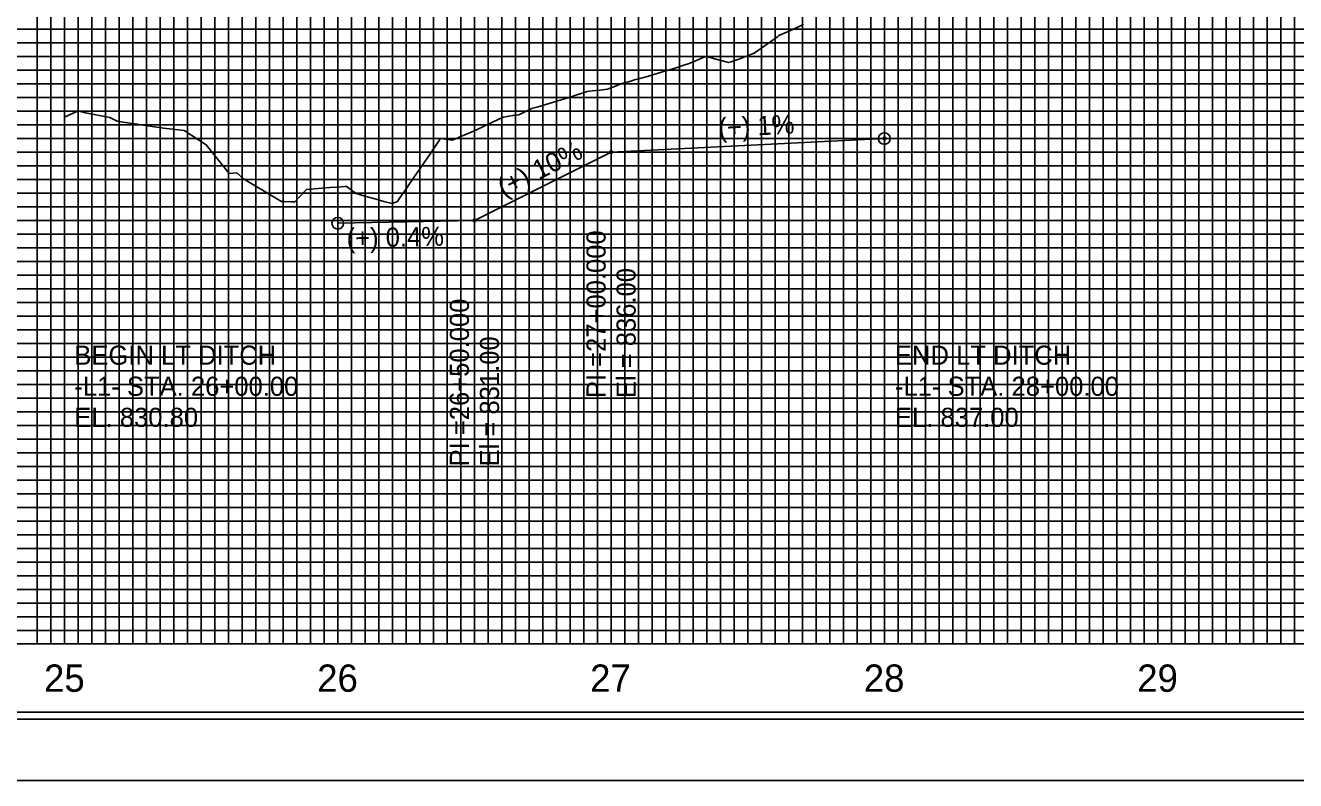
# Model space of a CAD drawing. Extents: x 570622 to 580296, y -55533 to -48575.
# Drawn here: x 570874.4 to 571339.1, y -53332.1 to -53055.6 of the extents above; entities that cross this region are included whole.
import ezdxf

# ---------------------------------------------------------------- set-up
doc = ezdxf.new("R2010")
doc.units = 0
for name, color, linetype in [('Exist Vertical Profile Ground Line', 7, 'Continuous'), ('Exist Vertical Profile Horizontal Axis Label Major', 7, 'Continuous'), ('Prop Vertical Profile Ditch Grade Left', 7, 'Continuous'), ('Prop Vertical Profile Ditch Grade Left Label', 7, 'Continuous'), ('Prop VPI Ditch Grade Left Label', 7, 'Continuous'), ('Sheet Cutting Line CELL', 7, 'Continuous'), ('Sheet DOT Grid CELL', 7, 'Continuous'), ('Sheet Layout Profile Border Port 2', 7, 'Continuous'), ('Sheet Plot Border Inside CELL', 7, 'Continuous'), ('Sheet Plot Border Outside CELL', 7, 'Continuous'), ('Sheet Profile CELL', 7, 'Continuous'), ('Sheet Profile Grid Major CELL', 7, 'Continuous'), ('Sheet Profile Grid Middle CELL', 7, 'Continuous'), ('Sheet Profile Grid Minor CELL', 7, 'Continuous')]:
    doc.layers.add(name, color=color, linetype=linetype)

msp = doc.modelspace()

# ---------------------------------------------------------------- linework, layer by layer
at = {"layer": 'Exist Vertical Profile Ground Line'}
msp.add_lwpolyline([(570888.69, -53089.16), (570893.66, -53086.84), (570896.35, -53087.58), (570905.28, -53089.28), (570907.95, -53090.63), (570909.32, -53090.91), (570911.07, -53091.22), (570924.97, -53093.18), (570932.45, -53094.08), (570940.58, -53099.31), (570948.99, -53109.85), (570951.75, -53109.6), (570954.16, -53111.83), (570966, -53118.85), (570968.09, -53120.08), (570968.82, -53120.11), (570971.65, -53120.22), (570972.95, -53120.26), (570974.47, -53118.62), (570977.29, -53115.65), (570980.12, -53115.45), (570982.94, -53115.24), (570985.77, -53115.01), (570988.59, -53114.78), (570991.41, -53114.53), (570991.81, -53114.49), (570994.24, -53116.27), (570995.48, -53117.17), (570997.06, -53117.64), (570999.89, -53118.47), (571002.71, -53119.27), (571005.53, -53120.06), (571008.57, -53120.87), (571010.53, -53120.07), (571011.18, -53119.14), (571014, -53115.06), (571016.83, -53110.95), (571019.65, -53106.82), (571022.48, -53102.66), (571025.3, -53098.47), (571026.24, -53097.06), (571028.12, -53097.3), (571030.64, -53097.59), (571030.95, -53097.46), (571033.77, -53096.27), (571036.59, -53095.04), (571039.42, -53093.79), (571042.24, -53092.51), (571045.07, -53091.21), (571047.89, -53089.88), (571049.39, -53089.16), (571050.71, -53088.97), (571053.54, -53088.53), (571054.92, -53088.31), (571056.36, -53087.62), (571059.19, -53086.26), (571059.61, -53086.05), (571062.01, -53085.38), (571064.83, -53084.57), (571067.66, -53083.74), (571070.48, -53082.87), (571073.3, -53081.98), (571076.13, -53081.06), (571078.95, -53080.12), (571079.89, -53079.79), (571081.78, -53079.6), (571084.6, -53079.29), (571087.42, -53078.9), (571090.25, -53077.83), (571092.65, -53076.91), (571093.07, -53076.79), (571095.89, -53076), (571097.3, -53075.59), (571098.72, -53075.2), (571101.54, -53074.41), (571104.37, -53073.59), (571107.19, -53072.75), (571110.01, -53071.88), (571112.84, -53070.99), (571115.66, -53070.07), (571116.91, -53069.65), (571118.49, -53069.02), (571121.31, -53067.88), (571123.57, -53066.94), (571124.13, -53067.11), (571126.96, -53067.93), (571129.78, -53068.72), (571131.68, -53069.23), (571132.6, -53068.92), (571135.43, -53067.93), (571138.25, -53066.93), (571141.08, -53065.82), (571143.9, -53063.83), (571146.72, -53061.81), (571149.55, -53059.78), (571150.11, -53059.37), (571152.37, -53058.35), (571155.19, -53057.06), (571158.02, -53055.74), (571159.14, -53055.21)], dxfattribs=at)
at = {"layer": 'Prop Vertical Profile Ditch Grade Left'}
msp.add_lwpolyline([(570988.69, -53128.05), (571038.69, -53127.05), (571088.69, -53102.05), (571188.69, -53097.05)], dxfattribs=at)
at = {"layer": 'Prop Vertical Profile Ditch Grade Left Label'}
for p, q in [((571188.69, -53098.05), (571188.69, -53182.05)), ((571088.69, -53103.05), (571088.69, -53196.19)), ((570988.69, -53128.05), (570988.69, -53182.05)), ((570988.69, -53182.05), (570889.59, -53182.05)), ((571287.94, -53182.05), (571188.69, -53182.05))]:
    msp.add_line(p, q, dxfattribs=at)
at = {"layer": 'Prop VPI Ditch Grade Left Label'}
for centre, radius in [((571188.69, -53097.05), 2.14), ((571188.69, -53097.05), 0.5), ((571088.69, -53102.05), 0.5), ((570988.69, -53128.05), 2.14), ((571038.69, -53127.05), 0.5)]:
    msp.add_circle(centre, radius, dxfattribs=at)
at = {"layer": 'Sheet Cutting Line CELL'}
msp.add_line((570621.69, -53332.05), (572305.69, -53332.05), dxfattribs=at)
at = {"layer": 'Sheet DOT Grid CELL'}
for p, q in [((570888.69, -52782.05), (570888.69, -53282.05)), ((570938.69, -52782.05), (570938.69, -53282.05)), ((570988.69, -52782.05), (570988.69, -53282.05)), ((571038.69, -52782.05), (571038.69, -53282.05)), ((571088.69, -52782.05), (571088.69, -53282.05)), ((571138.69, -52782.05), (571138.69, -53282.05)), ((571188.69, -52782.05), (571188.69, -53282.05)), ((571238.69, -52782.05), (571238.69, -53282.05)), ((571288.69, -52782.05), (571288.69, -53282.05)), ((571338.69, -52782.05), (571338.69, -53282.05)), ((570788.69, -53082.05), (572288.57, -53082.05)), ((570788.69, -53132.05), (572288.57, -53132.05)), ((570788.69, -53182.05), (572288.57, -53182.05)), ((570788.69, -53232.05), (572288.57, -53232.05))]:
    msp.add_line(p, q, dxfattribs=at)
at = {"layer": 'Sheet Layout Profile Border Port 2'}
msp.add_lwpolyline([(570838.69, -52782.05), (572238.69, -52782.05), (572238.69, -53282.05), (570838.69, -53282.05)], close=True, dxfattribs=at)
at = {"layer": 'Sheet Plot Border Inside CELL'}
msp.add_lwpolyline([(570634.69, -53309.6), (572301.19, -53309.6), (572301.19, -52254.5), (570634.69, -52254.5)], close=True, dxfattribs=at)
at = {"layer": 'Sheet Plot Border Outside CELL'}
msp.add_lwpolyline([(570621.69, -53332.05), (572305.69, -53332.05), (572305.69, -52232.05), (570621.69, -52232.05)], close=True, dxfattribs=at)
at = {"layer": 'Sheet Profile CELL'}
for p, q in [((572288.69, -53282.05), (570788.69, -53282.05)), ((570788.69, -53307.05), (572288.69, -53307.05))]:
    msp.add_line(p, q, dxfattribs=at)
msp.add_lwpolyline([(572288.69, -52257.05), (570788.69, -52257.05), (570788.69, -53307.05), (572288.69, -53307.05)], close=True, dxfattribs=at)
at = {"layer": 'Sheet Profile Grid Major CELL'}
for points in [[(570838.69, -52782.05), (570838.69, -53282.05), (570888.69, -53282.05), (570888.69, -52782.05), (570938.69, -52782.05), (570938.69, -53282.05), (570988.69, -53282.05), (570988.69, -52782.05), (571038.69, -52782.05), (571038.69, -53282.05), (571088.69, -53282.05), (571088.69, -52782.05), (571138.69, -52782.05), (571138.69, -53282.05), (571188.69, -53282.05), (571188.69, -52782.05), (571238.69, -52782.05), (571238.69, -53282.05), (571288.69, -53282.05), (571288.69, -52782.05), (571338.69, -52782.05), (571338.69, -53282.05), (571388.69, -53282.05)], [(572288.69, -53082.05), (570788.69, -53082.05), (570788.69, -53132.05), (572288.69, -53132.05)], [(572288.69, -53182.05), (570788.69, -53182.05), (570788.69, -53182.05), (570788.69, -53232.05), (572288.69, -53232.05)], [(572288.69, -53282.05), (570788.69, -53282.05)]]:
    msp.add_lwpolyline(points, dxfattribs=at)
at = {"layer": 'Sheet Profile Grid Middle CELL'}
for points in [[(570813.69, -52782.05), (570863.69, -52782.05), (570863.69, -53282.05), (570913.69, -53282.05), (570913.69, -52782.05), (570963.69, -52782.05), (570963.69, -53282.05), (571013.69, -53282.05), (571013.69, -52782.05), (571063.69, -52782.05), (571063.69, -53282.05), (571113.69, -53282.05), (571113.69, -52782.05), (571163.69, -52782.05), (571163.69, -53282.05), (571213.69, -53282.05), (571213.69, -52782.05), (571263.69, -52782.05), (571263.69, -53282.05), (571313.69, -53282.05), (571313.69, -52782.05), (571363.69, -52782.05)], [(572288.69, -53057.05), (570788.69, -53057.05), (570788.69, -53107.05), (572288.69, -53107.05)], [(572288.69, -53157.05), (570788.69, -53157.05), (570788.69, -53207.05), (572288.69, -53207.05)], [(572288.69, -53257.05), (570788.69, -53257.05)]]:
    msp.add_lwpolyline(points, dxfattribs=at)
at = {"layer": 'Sheet Profile Grid Minor CELL'}
for p, q in [((570838.69, -53062.05), (572238.69, -53062.05)), ((572238.69, -53067.05), (570838.69, -53067.05)), ((570838.69, -53072.05), (572238.69, -53072.05)), ((572238.69, -53077.05), (570838.69, -53077.05)), ((570838.69, -53087.05), (572238.69, -53087.05)), ((572238.69, -53092.05), (570838.69, -53092.05)), ((570838.69, -53097.05), (572238.69, -53097.05)), ((572238.69, -53102.05), (570838.69, -53102.05)), ((570838.69, -53112.05), (572238.69, -53112.05)), ((572238.69, -53117.05), (570838.69, -53117.05)), ((570838.69, -53122.05), (572238.69, -53122.05)), ((572238.69, -53127.05), (570838.69, -53127.05)), ((570838.69, -53137.05), (572238.69, -53137.05)), ((572238.69, -53142.05), (570838.69, -53142.05)), ((570838.69, -53147.05), (572238.69, -53147.05)), ((572238.69, -53152.05), (570838.69, -53152.05)), ((570838.69, -53162.05), (572238.69, -53162.05)), ((572238.69, -53167.05), (570838.69, -53167.05)), ((570838.69, -53172.05), (572238.69, -53172.05)), ((572238.69, -53177.05), (570838.69, -53177.05)), ((570838.69, -53187.05), (572238.69, -53187.05)), ((572238.69, -53192.05), (570838.69, -53192.05)), ((570838.69, -53197.05), (572238.69, -53197.05)), ((572238.69, -53202.05), (570838.69, -53202.05)), ((570838.69, -53212.05), (572238.69, -53212.05)), ((572238.69, -53217.05), (570838.69, -53217.05)), ((570838.69, -53222.05), (572238.69, -53222.05)), ((572238.69, -53227.05), (570838.69, -53227.05)), ((570838.69, -53237.05), (572238.69, -53237.05)), ((572238.69, -53242.05), (570838.69, -53242.05)), ((570838.69, -53247.05), (572238.69, -53247.05)), ((572238.69, -53252.05), (570838.69, -53252.05)), ((570838.69, -53262.05), (572238.69, -53262.05)), ((572238.69, -53267.05), (570838.69, -53267.05)), ((570838.69, -53272.05), (572238.69, -53272.05)), ((570838.69, -53277.05), (572238.69, -53277.05))]:
    msp.add_line(p, q, dxfattribs=at)
for points in [[(570878.69, -52782.05), (570878.69, -53282.05), (570883.69, -53282.05), (570893.69, -53282.05), (570898.69, -53282.05), (570898.69, -52782.05)], [(570883.69, -53282.05), (570883.69, -52782.05), (570893.69, -52782.05), (570893.69, -53282.05)], [(570903.69, -52782.05), (570903.69, -53282.05), (570908.69, -53282.05), (570908.69, -52782.05)], [(570918.69, -52782.05), (570918.69, -53282.05), (570923.69, -53282.05), (570923.69, -52782.05)], [(570928.69, -52782.05), (570928.69, -53282.05), (570933.69, -53282.05), (570933.69, -52782.05)], [(570943.69, -52782.05), (570943.69, -53282.05), (570948.69, -53282.05), (570948.69, -52782.05)], [(570953.69, -52782.05), (570953.69, -53282.05), (570958.69, -53282.05), (570958.69, -52782.05)], [(570968.69, -52782.05), (570968.69, -53282.05), (570973.69, -53282.05), (570973.69, -52782.05)], [(570978.69, -52782.05), (570978.69, -53282.05), (570983.69, -53282.05), (570983.69, -52782.05)], [(570993.69, -52782.05), (570993.69, -53282.05), (570998.69, -53282.05), (570998.69, -52782.05)], [(571003.69, -52782.05), (571003.69, -53282.05), (571008.69, -53282.05), (571008.69, -52782.05)], [(571018.69, -52782.05), (571018.69, -53282.05), (571023.69, -53282.05), (571023.69, -52782.05)], [(571028.69, -52782.05), (571028.69, -53282.05), (571033.69, -53282.05), (571033.69, -52782.05)], [(571043.69, -52782.05), (571043.69, -53282.05), (571048.69, -53282.05), (571048.69, -52782.05)], [(571053.69, -53282.05), (571058.69, -53282.05), (571058.69, -52782.05)], [(571053.69, -52782.05), (571053.69, -53282.05)], [(571068.69, -52782.05), (571068.69, -53282.05), (571073.69, -53282.05), (571073.69, -52782.05)], [(571078.69, -52782.05), (571078.69, -53282.05), (571083.69, -53282.05), (571083.69, -52782.05)], [(571093.69, -52782.05), (571093.69, -53282.05), (571098.69, -53282.05), (571098.69, -52782.05)], [(571103.69, -52782.05), (571103.69, -53282.05), (571108.69, -53282.05), (571108.69, -52782.05)], [(571118.69, -52782.05), (571118.69, -53282.05), (571123.69, -53282.05), (571123.69, -52782.05)], [(571128.69, -52782.05), (571128.69, -53282.05), (571133.69, -53282.05), (571133.69, -52782.05)], [(571143.69, -52782.05), (571143.69, -53282.05), (571148.69, -53282.05), (571148.69, -52782.05)], [(571153.69, -52782.05), (571153.69, -53282.05), (571158.69, -53282.05), (571158.69, -52782.05)], [(571168.69, -52782.05), (571168.69, -53282.05), (571173.69, -53282.05), (571173.69, -52782.05)], [(571178.69, -52782.05), (571178.69, -53282.05), (571183.69, -53282.05), (571183.69, -52782.05)], [(571193.69, -52782.05), (571193.69, -53282.05), (571198.69, -53282.05), (571198.69, -52782.05)], [(571203.69, -52782.05), (571203.69, -53282.05), (571208.69, -53282.05), (571208.69, -52782.05)], [(571218.69, -52782.05), (571218.69, -53282.05), (571223.69, -53282.05), (571223.69, -52782.05)], [(571228.69, -52782.05), (571228.69, -53282.05), (571233.69, -53282.05), (571233.69, -52782.05)], [(571243.69, -52782.05), (571243.69, -53282.05), (571248.69, -53282.05), (571248.69, -52782.05)], [(571253.69, -52782.05), (571253.69, -53282.05), (571258.69, -53282.05), (571258.69, -52782.05)], [(571268.69, -52782.05), (571268.69, -53282.05), (571273.69, -53282.05), (571273.69, -52782.05)], [(571278.69, -52782.05), (571278.69, -53282.05), (571283.69, -53282.05), (571283.69, -52782.05)], [(571293.69, -52782.05), (571293.69, -53282.05), (571298.69, -53282.05), (571298.69, -52782.05)], [(571303.69, -52782.05), (571303.69, -53282.05), (571308.69, -53282.05), (571308.69, -52782.05)], [(571318.69, -52782.05), (571318.69, -53282.05), (571323.69, -53282.05), (571323.69, -52782.05)], [(571328.69, -52782.05), (571328.69, -53282.05), (571333.69, -53282.05), (571333.69, -52782.05)]]:
    msp.add_lwpolyline(points, dxfattribs=at)

# ---------------------------------------------------------------- texts
at = {"layer": 'Exist Vertical Profile Horizontal Axis Label Major'}
for s, p in [('25', (570881.23, -53299.55)), ('26', (570981.17, -53299.55)), ('27', (571081.03, -53299.55)), ('28', (571181.16, -53299.55)), ('29', (571281.2, -53299.55))]:
    msp.add_text(s, height=10, dxfattribs=at).set_placement(p)
at = {"layer": 'Prop Vertical Profile Ditch Grade Left Label'}
for s, rotation, p in [('(+) 1%', 2.8624, (571128.12, -53096.58)), ('(+) 10%', 26.5651, (571049.4, -53118.64)), ('(+) 0.4%', 1.1458, (570991.99, -53136.97))]:
    msp.add_text(s, height=7, rotation=rotation, dxfattribs=at).set_placement(p)
at = {"layer": 'Prop VPI Ditch Grade Left Label'}
for s, p in [('PI =27+00.000', (571086.69, -53192.05)), ('PI =27+00.000', (571086.69, -53192.05)), ('El = 836.00', (571097.69, -53192.05)), ('El = 836.00', (571097.69, -53192.05)), ('PI =26+50.000', (571036.69, -53217.05)), ('El = 831.00', (571047.69, -53217.05))]:
    msp.add_text(s, height=7, rotation=90, dxfattribs=at).set_placement(p)
for s, p in [('BEGIN LT DITCH', (570892.31, -53179.83)), ('END LT DITCH', (571192.56, -53179.83)), ('-L1- STA. 26+00.00', (570892.31, -53191.21)), ('-L1- STA. 28+00.00', (571192.56, -53191.21)), ('EL. 830.80', (570892.31, -53202.58)), ('EL. 837.00', (571192.56, -53202.58))]:
    msp.add_text(s, height=7, dxfattribs=at).set_placement(p)

doc.saveas('drawing.dxf')
